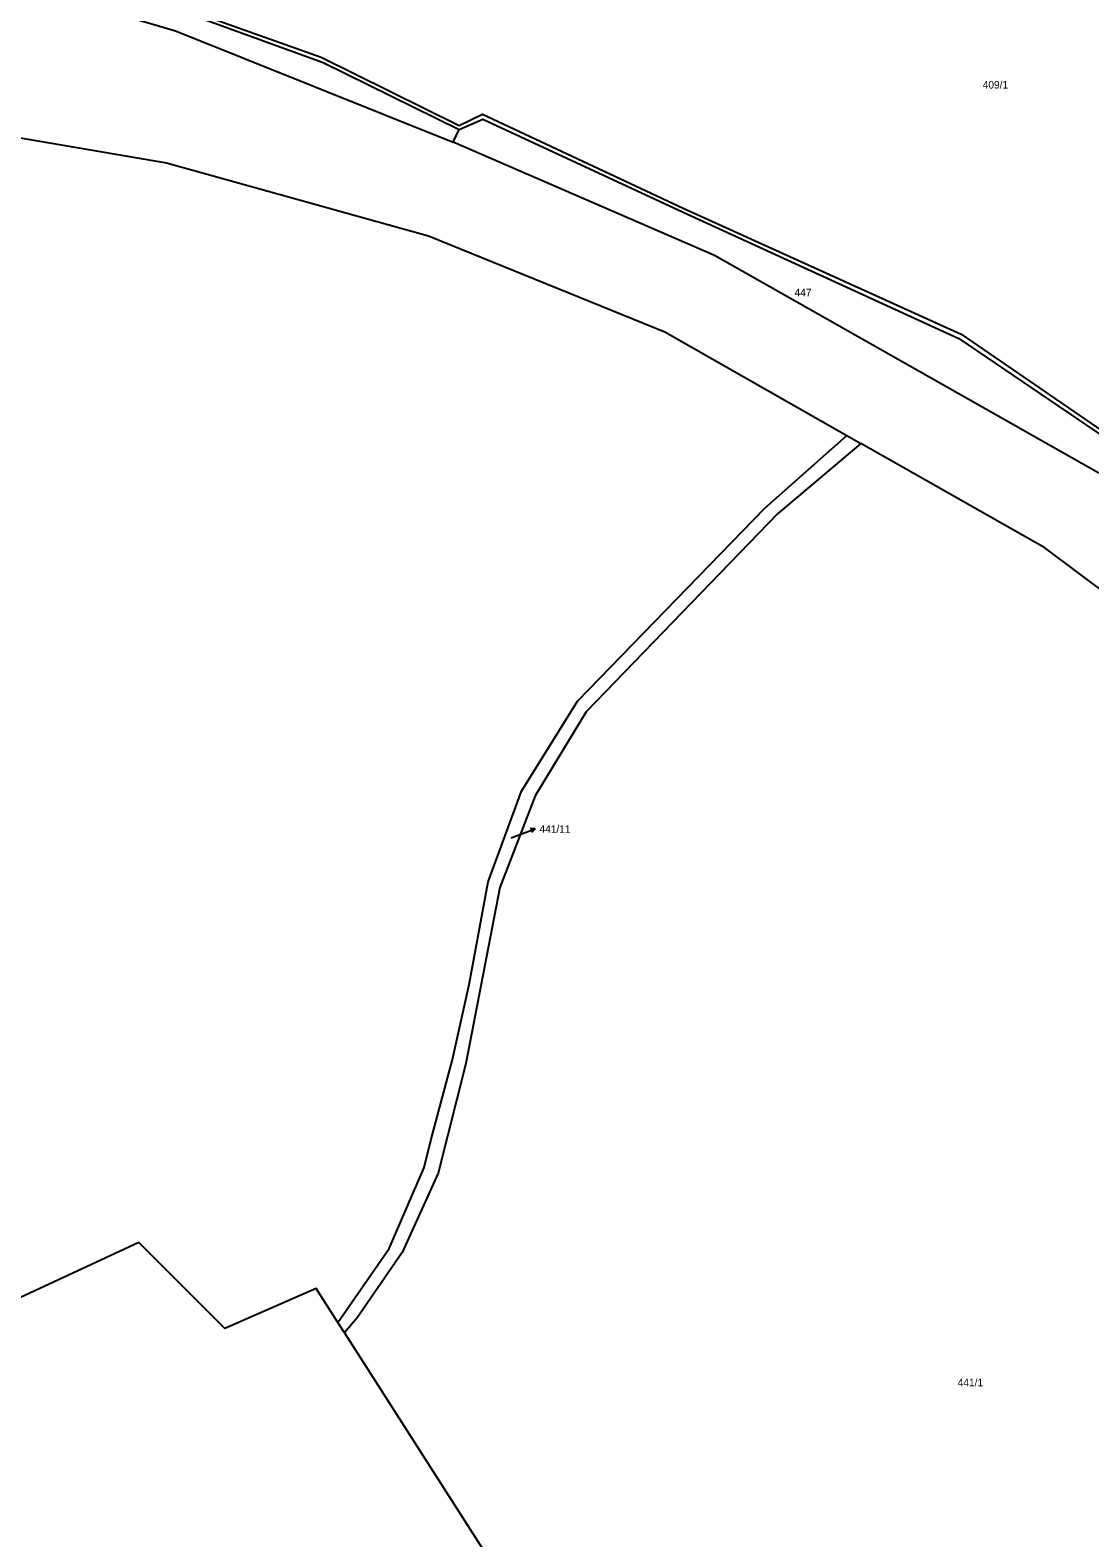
# Model space of a CAD drawing. Extents: x -880531 to -877616, y -1023932 to -1021350.
# Drawn here: x -880037.5 to -879800.4, y -1022931.1 to -1022593.9 of the extents above; entities that cross this region are included whole.
import ezdxf

# ---------------------------------------------------------------- set-up
doc = ezdxf.new("R2010")
doc.units = 0
for name, color, linetype in [('Hranice parcel', 7, 'Continuous'), ('Parcelní čísla', 7, 'Continuous'), ('Pop  PČ popisy', 7, 'Continuous'), ('Vnitřní kresba', 7, 'Continuous')]:
    doc.layers.add(name, color=color, linetype=linetype)

msp = doc.modelspace()

# ---------------------------------------------------------------- linework, layer by layer
at = {"layer": 'Hranice parcel'}
for p, q in [((-879942.81, -1022618.93), (-879941.5, -1022616.12)), ((-879854.76, -1022684.53), (-879851.64, -1022686.3)), ((-879967.14, -1022885.22), (-879968.62, -1022882.91))]:
    msp.add_line(p, q, dxfattribs=at)
for points in [[(-880166.5, -1022548.2), (-880166.5, -1022563), (-880091.71, -1022568.45), (-880004.96, -1022594.04), (-879942.81, -1022618.93)], [(-880109.86, -1022556.49), (-880041.33, -1022572.02), (-880004.82, -1022589.23), (-879971.92, -1022601.09), (-879941.5, -1022616.12)], [(-880085.09, -1022610.19), (-880006.95, -1022623.58), (-879948.33, -1022639.86), (-879895.51, -1022661.38), (-879854.76, -1022684.53)], [(-879941.5, -1022616.12), (-879936.23, -1022613.81), (-879891.4, -1022634.58), (-879829.75, -1022662.83), (-879795.38, -1022686.18)], [(-879798.38, -1022692.94), (-879884.35, -1022644.31), (-879942.81, -1022618.93)], [(-879968.62, -1022882.91), (-879957.17, -1022866.34), (-879949.33, -1022848.2), (-879947.87, -1022842.2), (-879942.99, -1022824.06), (-879939.26, -1022807.33), (-879934.98, -1022784.36), (-879927.58, -1022764.09), (-879915.03, -1022743.98), (-879873.13, -1022700.8), (-879854.76, -1022684.53)], [(-879851.64, -1022686.3), (-879870.27, -1022702.07), (-879913.06, -1022746.31), (-879924.51, -1022765.15), (-879932.41, -1022785.62), (-879939.99, -1022824.94), (-879946.18, -1022849.51), (-879954.28, -1022867.24), (-879964.33, -1022881.82), (-879967.14, -1022885.22)], [(-879678.3, -1022825.24), (-879709.21, -1022794.23), (-879764.96, -1022743.66), (-879810.51, -1022709.67), (-879851.64, -1022686.3)], [(-879968.62, -1022882.91), (-879973.51, -1022875.27), (-879993.92, -1022884.22), (-880013.19, -1022864.99), (-880049.16, -1022881.72), (-880101.32, -1022907.34)], [(-879967.14, -1022885.22), (-879926.31, -1022949.08), (-879906.41, -1022994.89), (-879898.19, -1023014.67), (-879871.37, -1023071.65), (-879843.32, -1023124.08), (-879802.44, -1023195.78)]]:
    msp.add_lwpolyline(points, dxfattribs=at)
at = {"layer": 'Pop  PČ popisy'}
for p, q in [((-879927.35, -1022773.56), (-879924.53, -1022772.534)), ((-879924.53, -1022772.534), (-879925.642, -1022772.406)), ((-879924.53, -1022772.534), (-879925.3, -1022773.347)), ((-879929.9, -1022774.48), (-879927.35, -1022773.56))]:
    msp.add_line(p, q, dxfattribs=at)
at = {"layer": 'Vnitřní kresba'}
for points in [[(-880146.98, -1022500.44), (-880097.84, -1022509.25), (-880108.97, -1022555.86), (-880040.89, -1022570.99), (-880004.48, -1022588.49), (-879972.36, -1022599.94)], [(-879972.36, -1022599.94), (-879941.51, -1022615.23), (-879936.26, -1022612.69), (-879891.42, -1022633.68)], [(-879891.42, -1022633.68), (-879829.22, -1022661.84), (-879795.19, -1022685.23), (-879749.08, -1022711.64), (-879683.08, -1022780.5)]]:
    msp.add_lwpolyline(points, dxfattribs=at)

# ---------------------------------------------------------------- texts
at = {"layer": 'Parcelní čísla'}
for s, p in [('409/1', (-879824.38, -1022606.95)), ('447', (-879866.48, -1022653.41)), ('441/11', (-879923.53, -1022773.39)), ('441/1', (-879829.98, -1022897.17))]:
    msp.add_text(s, height=1.7, dxfattribs=at).set_placement(p)

doc.saveas('drawing.dxf')
